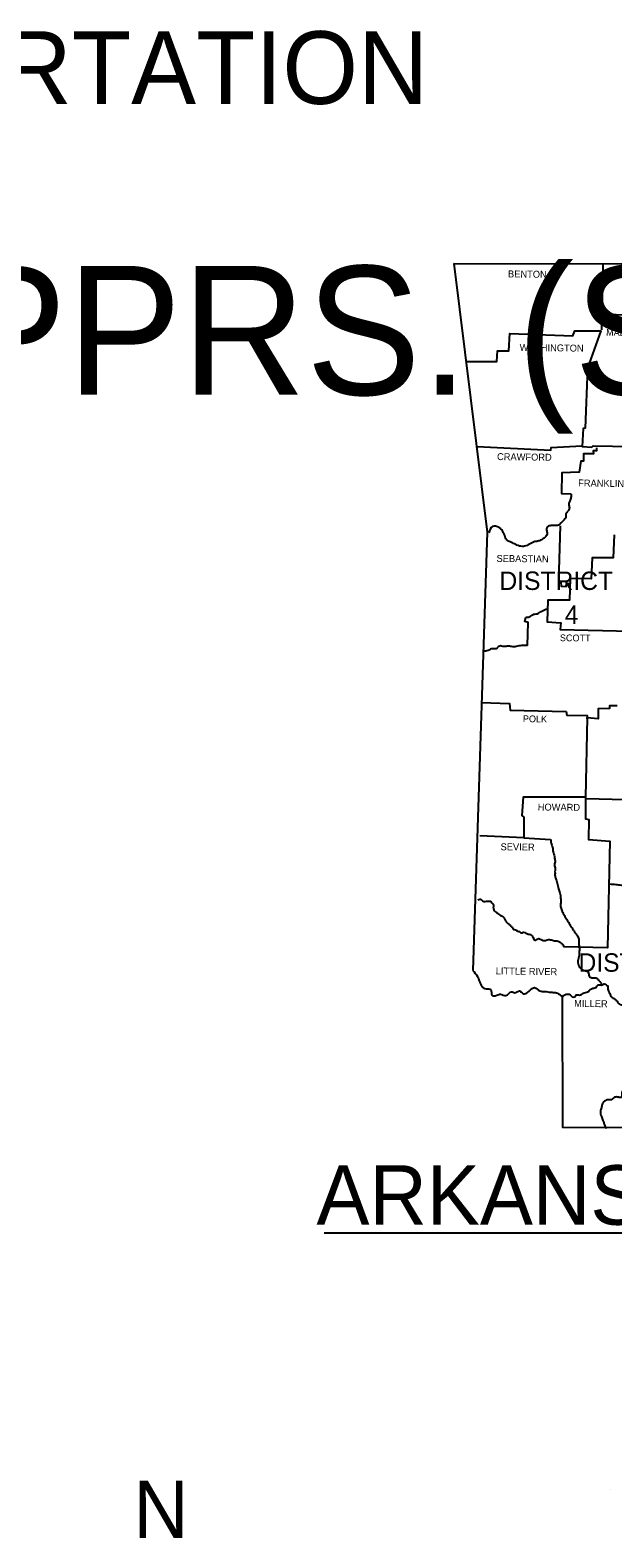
# Model space of a CAD drawing. Extents: x 152 to 3426, y 67 to 2142.
# Drawn here: x 2447 to 2800, y 1185 to 2098 of the extents above; entities that cross this region are included whole.
import ezdxf

# ---------------------------------------------------------------- set-up
doc = ezdxf.new("R2010")
doc.units = 0
for name, color, linetype in [('R_Border', 7, 'Continuous'), ('R_Draft', 7, 'Continuous'), ('R_Grid', 7, 'Continuous'), ('S_AREA_CALC', 7, 'Continuous')]:
    doc.layers.add(name, color=color, linetype=linetype)

msp = doc.modelspace()

# ---------------------------------------------------------------- linework, layer by layer
at = {"layer": 'S_AREA_CALC'}
for p, q in [((2625.16, 1369.37), (3289.7, 1369.37)), ((2798.77, 1214.21), (2798.77, 1214.21))]:
    msp.add_line(p, q, dxfattribs=at)
for points in [[(2703.71, 1956.42), (2861.92, 1956.32), (3000.75, 1956.61), (3164.54, 1959.16), (3240.46, 1960.92)], [(2703.71, 1956.42), (2723.96, 1793.81), (2715.15, 1528.37)], [(2794.01, 1955.83), (2793.13, 1916.21)], [(2793.82, 1925.89), (2817.89, 1925.11), (2818.47, 1921.98), (2821.8, 1921.88), (2821.7, 1919.92), (2824.05, 1919.34), (2824.25, 1908.67), (2827.28, 1907.99), (2827.48, 1903.78), (2831.78, 1903.19), (2831.98, 1899.28), (2840.49, 1898.4), (2862.4, 1898.89), (2862.6, 1955.15)], [(2711.44, 1897.22), (2729.73, 1897.13), (2730.22, 1903.58), (2736.97, 1903.58), (2737.56, 1914.05), (2775.72, 1912.68), (2776.89, 1915.62), (2792.64, 1915.72), (2784.72, 1893.02), (2783.15, 1856.72), (2781.98, 1856.62), (2781.39, 1845.66), (2787.17, 1845.17), (2788.05, 1846.05), (2834.72, 1845.17), (2835.21, 1839.99)], [(2717.89, 1845.56), (2762.41, 1843.51), (2762.61, 1845.08), (2781.2, 1845.96)], [(2790, 1844.78), (2790, 1843.02), (2788.14, 1843.02), (2788.24, 1841.26), (2782.27, 1841.16), (2782.18, 1836.76), (2780.51, 1836.76), (2779.63, 1830.2), (2769.06, 1829.71), (2768.97, 1817.29), (2774.64, 1816.9)], [(2800.86, 1792.24), (2800.18, 1778.25), (2787.46, 1778.15), (2786.77, 1765.43), (2774.15, 1765.73), (2773.76, 1752.62), (2760.55, 1752.52), (2760.16, 1739.41), (2768.48, 1738.92), (2768.18, 1734.91), (2810.65, 1733.73)], [(2767.99, 1797.53), (2767.01, 1763.87), (2768.48, 1763.48), (2768.77, 1761.13), (2771.71, 1760.93), (2772, 1762.6), (2774.35, 1762.99)], [(2748.32, 1725.22), (2748.62, 1739.02), (2746.66, 1739.6), (2747.25, 1742.25)], [(2720.54, 1690.59), (2737.46, 1690), (2737.85, 1685.89), (2771.71, 1685.2), (2772.1, 1683.05), (2784.43, 1682.66), (2784.33, 1680.8)], [(2802.53, 1688.53), (2797.93, 1688.53), (2798.03, 1686.97), (2791.18, 1686.77), (2791.08, 1680.8), (2784.43, 1681.39), (2783.35, 1633.25), (2745.68, 1633.35), (2744.8, 1622.19), (2746.17, 1621.22), (2746.07, 1608.69), (2719.36, 1609.87)], [(2783.35, 1633.25), (2783.35, 1620.24), (2785.5, 1619.85), (2785.31, 1607.71), (2798.22, 1606.74), (2796.66, 1542.06), (2770.04, 1542.75)], [(2783.55, 1632.57), (2839.51, 1631.1)], [(2746.07, 1608.69), (2762.31, 1607.71)], [(2769.26, 1512.61), (2769.46, 1433.46), (3128.04, 1432.87)]]:
    msp.add_lwpolyline(points, dxfattribs=at)
for points in [[(2774.64, 1816.9), (2774.64, 1814.84), (2773.86, 1812.69), (2773.37, 1810.83), (2773.66, 1808.39), (2772.78, 1806.43), (2771.51, 1804.86), (2771.51, 1802.91), (2770.04, 1800.85), (2768.48, 1799.29), (2767.11, 1798.01), (2764.66, 1797.82), (2762.61, 1797.72), (2760.55, 1797.04), (2759.77, 1795.57), (2760.16, 1793.32), (2759.38, 1791.17), (2757.32, 1789.5), (2755.07, 1788.43), (2752.73, 1788.03), (2749.5, 1786.47), (2746.56, 1785.2), (2743.43, 1785.39), (2740.5, 1786.66), (2737.85, 1787.84), (2735.8, 1789.01), (2734.14, 1792.63), (2733.06, 1794.59), (2731.2, 1796.55), (2728.95, 1797.33), (2727.09, 1797.13), (2724.84, 1793.32)], [(2747.25, 1742.25), (2749.4, 1742.44), (2751.45, 1743.81), (2754.19, 1744.4), (2756.93, 1745.87), (2760.36, 1747.43)], [(2748.32, 1725.22), (2745.49, 1725.12), (2742.26, 1724.73), (2739.32, 1724.34), (2736.68, 1724.83), (2734.23, 1724.44), (2732.57, 1724.83), (2730.52, 1724.34), (2729.34, 1723.17), (2726.9, 1723.17), (2725.13, 1722.38), (2722.3, 1721.7)], [(2762.31, 1607.71), (2762.8, 1604.78), (2763.68, 1602.24), (2763.78, 1600.28), (2764.66, 1597.34), (2764.66, 1596.27), (2764.96, 1594.11), (2764.56, 1592.94), (2765.05, 1590.59), (2764.96, 1588.83), (2764.96, 1587.36), (2765.05, 1584.92), (2765.84, 1582.76), (2766.62, 1579.54), (2767.11, 1577.87), (2767.89, 1575.33), (2768.38, 1572.2), (2768.48, 1569.85), (2768.28, 1567.7), (2768.87, 1565.25), (2769.95, 1562.81), (2771.32, 1560.46), (2772.98, 1557.82), (2774.15, 1555.76), (2775.62, 1553.51), (2776.79, 1551.65), (2778.56, 1549.3), (2779.34, 1547.35), (2779.34, 1544.61), (2779.73, 1542.06), (2779.63, 1539.23), (2779.44, 1536.68), (2778.75, 1533.16), (2779.24, 1531.5), (2781.1, 1529.05), (2782.27, 1528.37), (2784.33, 1527.97), (2785.31, 1526.6), (2785.89, 1524.55), (2787.95, 1523.86), (2790.2, 1523.67), (2791.27, 1522.49), (2792.74, 1520.93), (2793.23, 1520.15)], [(2798.03, 1580.71), (2801.74, 1580.42), (2805.17, 1580.03), (2807.81, 1579.73), (2810.55, 1578.75), (2813, 1577.87), (2814.56, 1577.19), (2817.2, 1577.38), (2819.45, 1576.89), (2822, 1576.01), (2823.86, 1574.35), (2825.03, 1573.08), (2827.28, 1572.59), (2829.14, 1572.88), (2831.39, 1572.69), (2833.93, 1571.9), (2835.99, 1572), (2837.65, 1572.39), (2839.61, 1572.88), (2842.05, 1573.08), (2843.91, 1572.69), (2846.36, 1572.59), (2849.2, 1572.88), (2852.72, 1571.9)], [(2718.19, 1571.22), (2720.34, 1571.32), (2721.81, 1570.05), (2722.69, 1570.14), (2724.25, 1570.34), (2725.72, 1570.24), (2726.8, 1569.36), (2727.68, 1567.8), (2727.58, 1566.33), (2727.68, 1565.74), (2728.36, 1564.47), (2729.54, 1563.49), (2730.81, 1562.51), (2731.98, 1561.73), (2733.94, 1560.46), (2734.14, 1560.07), (2734.92, 1558.5), (2735.9, 1557.23), (2737.07, 1556.45), (2738.34, 1555.08), (2738.93, 1554.49), (2739.91, 1553.12), (2740.98, 1553.02), (2742.45, 1552.14), (2743.53, 1551.85), (2744.7, 1551.06), (2745.88, 1551.46), (2747.34, 1550.87), (2749.3, 1550.28), (2750.38, 1550.09), (2751.65, 1548.23), (2752.92, 1546.66), (2754.49, 1547.54), (2757.42, 1546.66), (2759.28, 1546.56), (2760.94, 1547.05), (2762.22, 1546.96), (2764.56, 1546.37), (2766.03, 1546.37), (2767.6, 1545.78), (2769.06, 1544.61), (2770.04, 1543.34), (2770.04, 1542.75)], [(2715.15, 1528.37), (2717.99, 1524.65), (2719.17, 1522.01), (2720.83, 1518.58), (2723.28, 1517.21), (2726.11, 1516.72), (2726.7, 1513.4), (2729.63, 1513.3), (2731.98, 1513.98), (2735.21, 1513.1), (2738.64, 1515.45), (2740.59, 1514.86), (2743.43, 1516.04), (2745.58, 1514.28), (2749.3, 1515.84), (2752.63, 1517.99), (2755.76, 1515.94), (2758.79, 1515.65), (2762.41, 1515.16), (2765.25, 1514.96), (2767.79, 1513.69), (2769.65, 1512.42), (2769.26, 1512.61)], [(2769.26, 1512.61), (2772.68, 1514.08), (2774.15, 1513.59), (2775.42, 1512.32), (2776.89, 1512.32), (2777.67, 1513.49), (2779.14, 1513.59), (2780.32, 1513.49), (2781.59, 1514.28), (2782.66, 1514.77), (2784.13, 1515.25), (2785.21, 1515.65), (2786.19, 1516.72), (2787.95, 1517.6), (2790, 1518.29), (2790.59, 1519.27), (2791.57, 1519.66), (2793.52, 1519.56), (2794.8, 1520.15), (2795.87, 1519.66), (2796.85, 1518.97), (2797.05, 1516.43), (2797.83, 1515.06), (2799, 1512.61), (2800.67, 1511.34), (2802.23, 1510.07), (2802.82, 1509.29), (2804.48, 1507.82), (2805.95, 1507.33), (2806.64, 1506.25), (2807.71, 1503.71), (2809.28, 1501.46)], [(2809.28, 1501.46), (2808.69, 1498.62), (2808.59, 1496.37), (2809.08, 1493.73), (2808.59, 1492.46), (2809.38, 1490.6), (2810.84, 1489.13), (2811.92, 1487.57), (2812.6, 1485.32), (2811.72, 1482.77), (2812.7, 1480.13), (2813.58, 1479.15), (2814.07, 1477.59), (2813.39, 1474.55), (2812.51, 1472.3), (2810.55, 1470.05), (2809.96, 1468.98), (2810.26, 1467.51), (2810.74, 1465.16), (2810.26, 1464.48), (2808.98, 1462.81), (2808.59, 1460.95), (2807.71, 1459.39), (2806.73, 1456.55), (2805.46, 1454.2), (2805.27, 1451.56), (2803.31, 1451.56), (2801.06, 1451.56), (2799, 1450.09), (2797.15, 1450), (2794.89, 1449.11), (2793.52, 1447.26), (2793.04, 1445.2), (2792.45, 1443.24), (2793.04, 1439.92), (2793.92, 1437.57), (2794.6, 1435.71), (2795.78, 1432.68)]]:
    msp.add_spline(points, degree=3, dxfattribs=at)

# ---------------------------------------------------------------- texts
at = {"layer": 'R_Border'}
for s, height, p in [('ARKANSAS DEPARTMENT OF TRANSPORTATION', 44.03, (1288.05, 2053.11)), ('EASSIS CREEK STR. & APPRS. (S)', 78, (1170.86, 1876.96)), ('ARKANSAS HIGHWAY DISTRICT 10', 36, (2620.5, 1374.37))]:
    msp.add_text(s, height=height, dxfattribs=at).set_placement(p)
for s, height, rotation, p in [('BENTON', 4.207, 359.25271, (2736.48, 1948.1)), ('MADISON', 4.109, 359.09062, (2795.87, 1912.78)), ('WASHINGTON', 4.206, 359.23201, (2743.53, 1903.58)), ('CRAWFORD', 4.206, 359.27706, (2729.83, 1837.44)), ('FRANKLIN', 4.207, 359.18154, (2778.95, 1821.5)), ('SEBASTIAN', 4.206, 359.28159, (2729.54, 1775.8)), ('SCOTT', 4.109, 359.40628, (2767.89, 1727.76)), ('POLK', 4.108, 359.21518, (2745.49, 1678.75)), ('HOWARD', 4.207, 359.51446, (2754.49, 1625.23)), ('SEVIER', 4.207, 359.42706, (2731.98, 1601.16)), ('LITTLE RIVER', 4.2073, 359.16968, (2729.05, 1526.02)), ('MILLER', 4.206, 359.13195, (2776.5, 1506.35))]:
    msp.add_text(s, height=height, rotation=rotation, dxfattribs=at).set_placement(p)
at = {"layer": 'R_Draft'}
msp.add_text('N', height=34.62, dxfattribs=at).set_placement((2509.57, 1184.74))
at = {"layer": 'R_Grid'}
for s, height, p in [('DISTRICT', 11.154, (2731.3, 1758.78)), ('4', 11.15, (2770.92, 1738.23)), ('DISTRICT', 11.154, (2779.19, 1527.57))]:
    msp.add_text(s, height=height, dxfattribs=at).set_placement(p)

doc.saveas('drawing.dxf')
